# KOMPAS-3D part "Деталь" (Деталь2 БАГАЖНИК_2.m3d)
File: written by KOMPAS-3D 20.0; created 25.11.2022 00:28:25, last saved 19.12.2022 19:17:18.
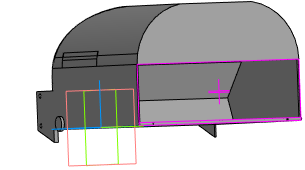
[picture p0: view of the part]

Document properties: Полное имя файла: C:\Users\Семья\Desktop\ДЕТАЛИ ДЛЯ СБОРЩИКА БОРЩЕВИКА\ДЕТАЛИ ДЛЯ ФИНАЛА\Деталь2 БАГАЖНИК_2.m3d

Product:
- Part/product: Деталь
    Масса: 0.563802
  - Body: Тело 2
      Масса: 0.0012587
  - Body: Тело 1
      Масса: 0.533874

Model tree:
1. Эскиз:1
2. Элемент выдавливания:1
     Расстояние 1 = 120
3. Эскиз:2  (with: Элемент выдавливания:1)
4. Эскиз:3  (with: Элемент выдавливания:1, Элемент выдавливания:2)
5. Элемент выдавливания:3
     Расстояние 2 = 1
6. Элемент выдавливания:7
     Расстояние 2 = 1
7. Элемент выдавливания:8
     Расстояние 2 = 0.5
8. Эскиз:5  (with: Элемент выдавливания:1, Элемент выдавливания:3, Элемент выдавливания:7)
9. Эскиз:6  (with: Элемент выдавливания:1, Элемент выдавливания:7)
10. Элемент выдавливания:10
     Расстояние 2 = 120
11. Эскиз:7  (with: Элемент выдавливания:7)
12. Элемент выдавливания:11
     Расстояние 1 = 119
13. Элемент выдавливания:12
     Расстояние 2 = 1
14. Эскиз:9  (with: Элемент выдавливания:1)
15. Эскиз:10  (with: Элемент выдавливания:1, Элемент выдавливания:3)
16. Элемент выдавливания:15  (with: Элемент выдавливания:10)
     Расстояние 2 = 119.781
17. Элемент выдавливания:16
     Расстояние 2 = 134
18. Эскиз:11  (with: Элемент выдавливания:11, Элемент выдавливания:16)
19. Элемент выдавливания:17
     Расстояние 2 = 10
20. Эскиз:12  (with: Элемент выдавливания:17)
21. Элемент выдавливания:18  (with: Элемент выдавливания:17)
     Расстояние 1 = 54
22. Эскиз:13  (with: Элемент выдавливания:17)
23. Элемент выдавливания:19  (with: Элемент выдавливания:17)
     Расстояние 1 = 54
24. Эскиз:14  (with: Элемент выдавливания:1, Элемент выдавливания:16)
25. Элемент выдавливания:21
     Расстояние 2 = 1
26. Эскиз:15  (with: Элемент выдавливания:1, Элемент выдавливания:21)
27. Элемент выдавливания:22
     Расстояние 2 = 10
28. Эскиз:16  (with: Элемент выдавливания:1, Элемент выдавливания:21)
29. Элемент выдавливания:23
     Расстояние 2 = 10
30. Элемент выдавливания:24  (with: Элемент выдавливания:1)
     Расстояние 1 = 1
31. Эскиз:17  (with: Элемент выдавливания:1, Элемент выдавливания:21, Элемент выдавливания:23)
32. Эскиз:19  (with: Элемент выдавливания:1)
33. Элемент выдавливания:26
     Расстояние 2 = 1
34. Эскиз:20  (with: Элемент выдавливания:1, Элемент выдавливания:26)
35. Элемент выдавливания:27
     Расстояние 2 = 1
36. Эскиз:21  (with: Элемент выдавливания:12, Элемент выдавливания:19, Элемент выдавливания:27)
37. Элемент выдавливания:29
     Расстояние 1 = 2
38. Эскиз:22  (with: Элемент выдавливания:12)
39. Элемент выдавливания:30
     Расстояние 2 = 10
40. Эскиз:23  (with: Элемент выдавливания:1, Элемент выдавливания:30)
41. Элемент выдавливания:31
     Расстояние 1 = 1
42. Эскиз:24  (with: Элемент выдавливания:31)
43. Элемент выдавливания:32
     Расстояние 1 = 2
44. Эскиз:25  (with: Элемент выдавливания:7, Элемент выдавливания:11, Элемент выдавливания:24)
45. Элемент выдавливания:33  (with: Элемент выдавливания:1)
     Расстояние 1 = 119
